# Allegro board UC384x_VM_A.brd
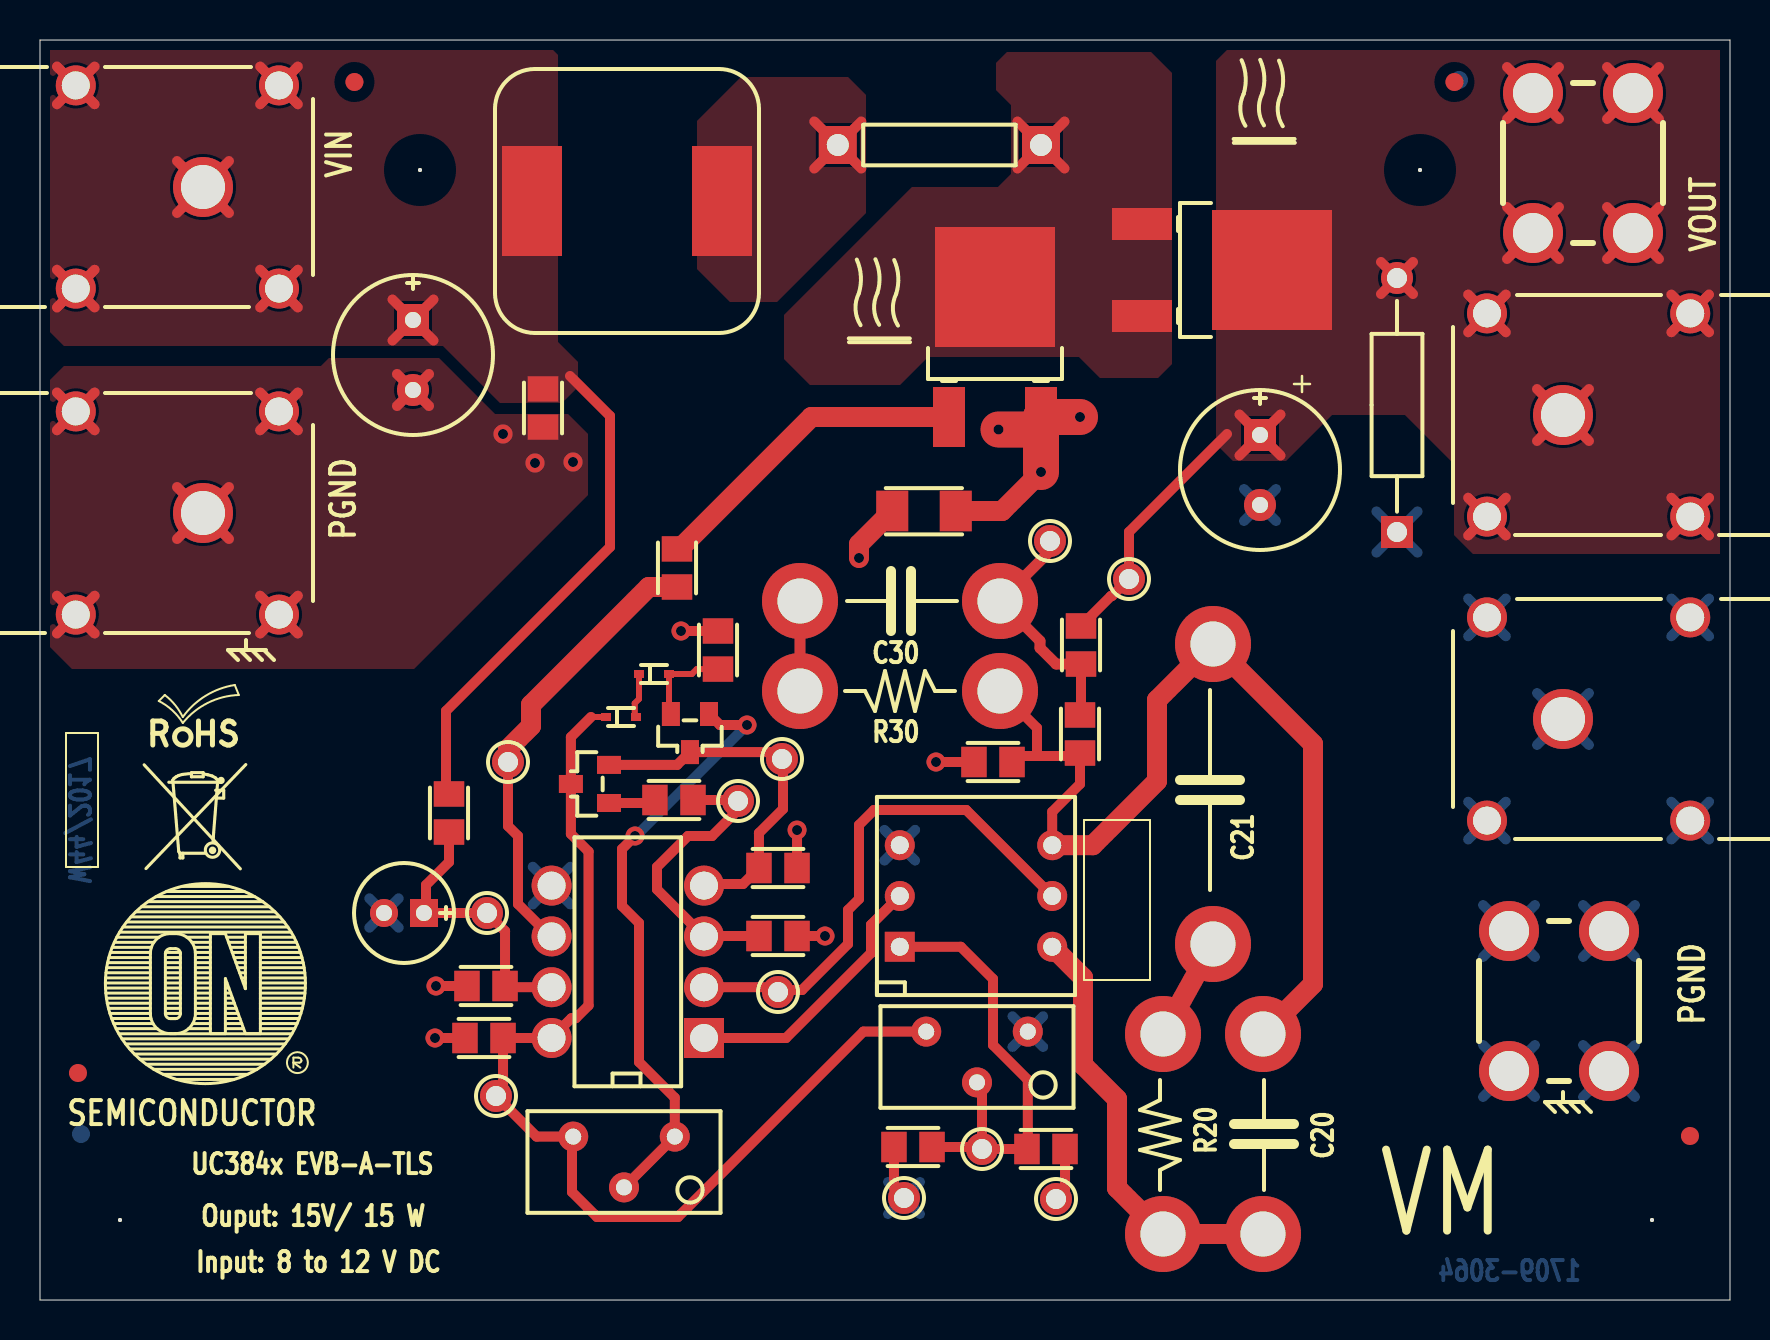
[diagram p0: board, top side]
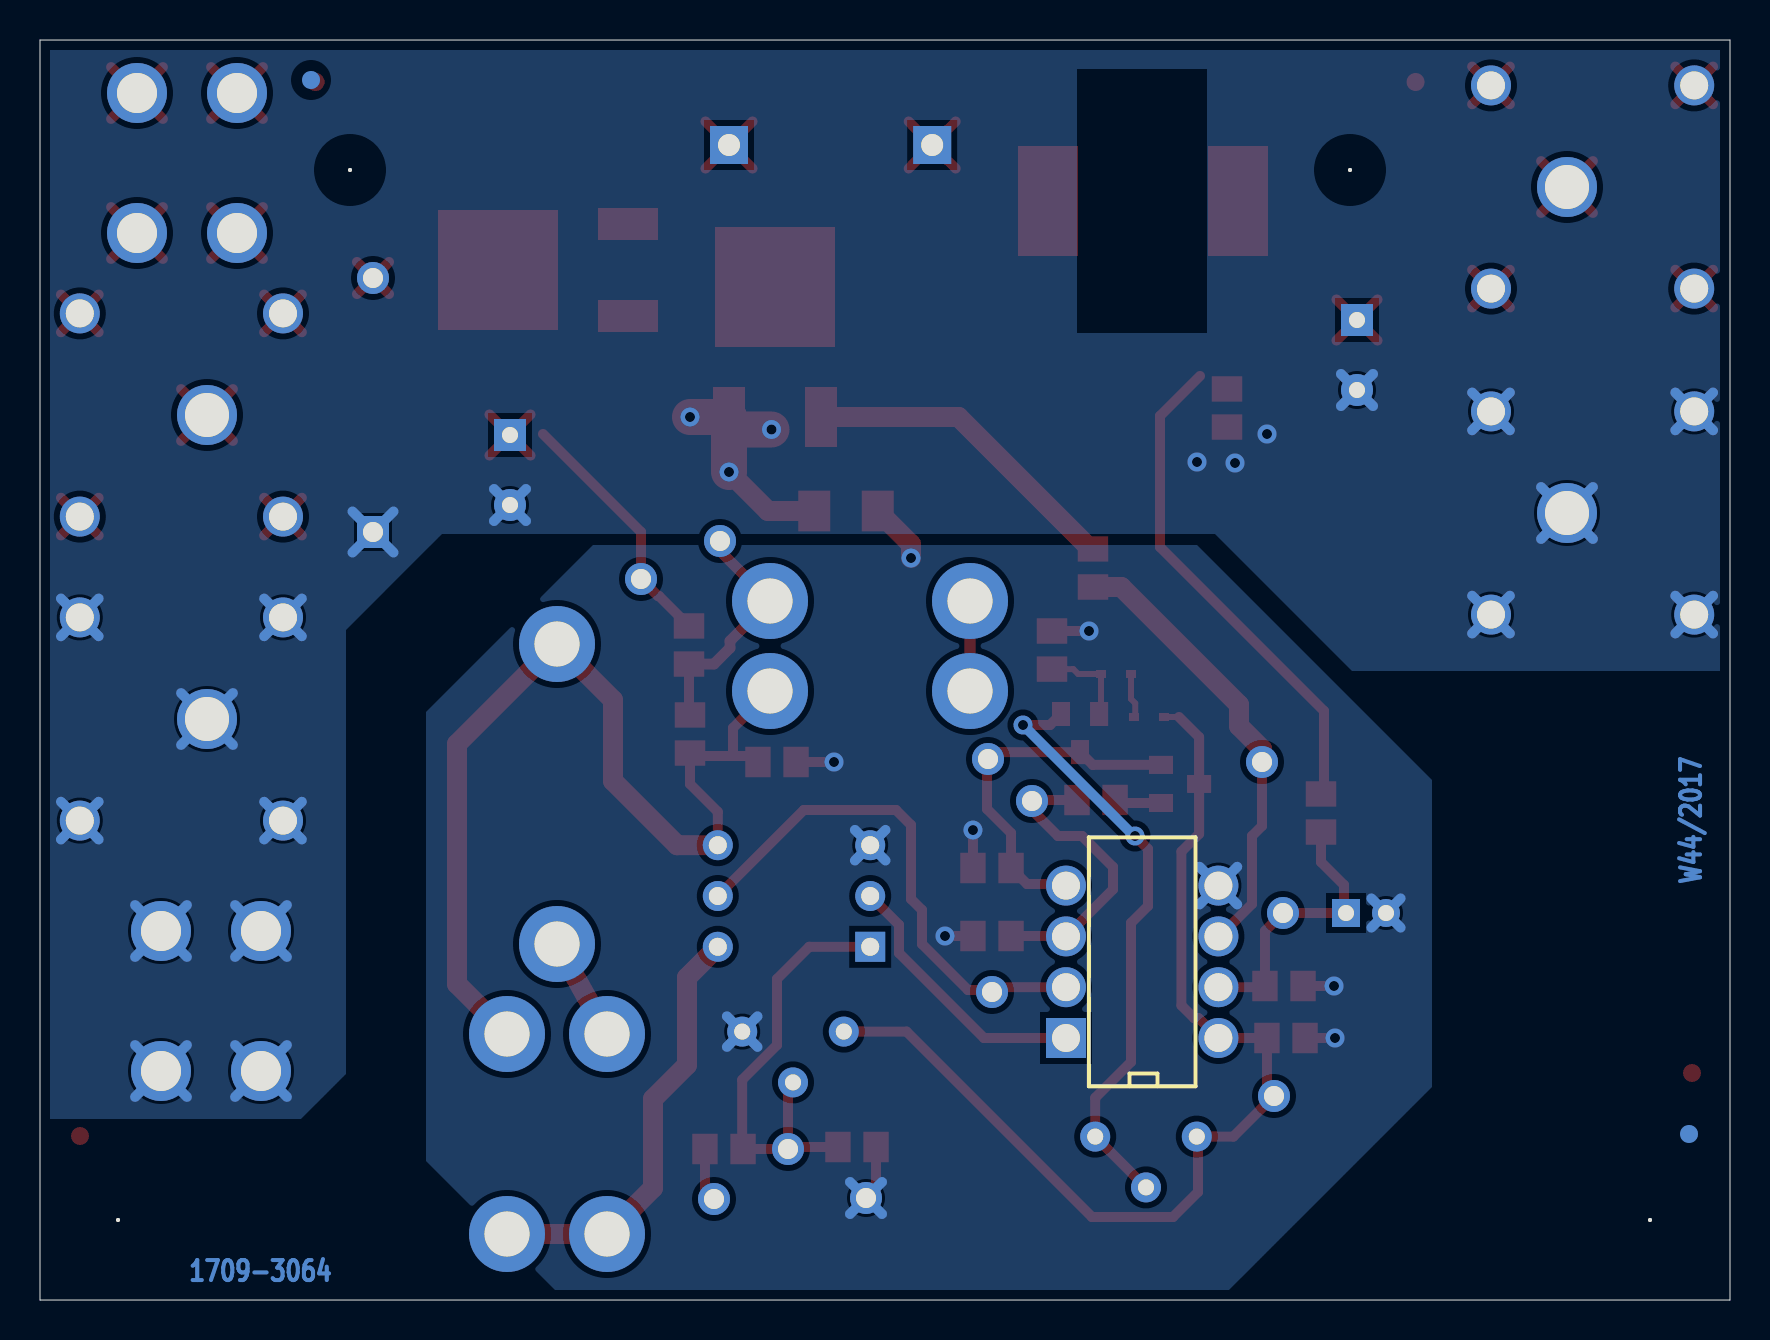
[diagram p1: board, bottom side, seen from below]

Outline 84.5 x 63 mm; copper layers: TOP, IN1, IN2, BOTTOM. Coordinates in mm from the lower left corner of the outline.
Outline path: 0,63 0,0 84.5,0 84.5,63 0,63

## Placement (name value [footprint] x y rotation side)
ACM_H  TEST POINT  [TP]  50.8 5.05 180 top
ACM_L  TEST POINT  [TP]  43.2 5.1 180 top
C1  100nF  [0805]  22.2 13.1 180 top
C1A  D  [PLOT_5380598-2]  58.65 32.8 270 top
C1B  D  [PLOT_5380598-2]  58.65 17.8 270 top
C2A  D  [PLOT_5380598-2]  61.15 13.3 270 top
C2B  D  [PLOT_5380598-2]  61.15 3.3 270 top
C3  2.2uF  [CAPA_CH_D5_H11_P2]  18.2 19.35 180 top
C3A  D  [PLOT_5380598-2]  38 34.95 0 top
C3B  D  [PLOT_5380598-2]  48 34.95 0 top
C4  220uF  [CAPA_CH_D8_H12_P3V5]  61 41.5 270 top
C5  220uF  [CAPA_CH_D8_H12_P3V5]  18.65 47.25 270 top
C6  1uF  [0805]  25.15 44.6 270 top
C7  100nF  [0805]  22.3 15.7 180 top
C8  100nF  [0805]  43.65 7.65 180 top
C9  2.2uF  [0805]  50.3 7.55 180 top
CB1  target_cms  [MIRE_LOW]  2.05 8.3 180 bottom
CB2  target_cms  [MIRE_LOW]  70.95 61 180 bottom
CB3  target_cms  [MIRE_LOW]  1.9 11.35 0 top
CB4  target_cms  [MIRE_LOW]  70.72 60.9 0 top
CB5  target_cms  [MIRE_LOW]  82.5 8.2 0 top
CB6  target_cms  [MIRE_LOW]  15.72 60.9 0 top
CMP  TEST POINT  [TP]  36.9 15.4 0 top
CT  1nF  [0805]  36.9 21.6 0 top
D1  1N4148  [SOD523]  29.05 29.15 0 top
D2  1N4148  [SOD523]  30.7 31.3 0 top
D3  MBRD1045T4G  [DPAK_TO252]  60 51.5 270 top
DRV  TEST POINT  [TP]  23.4 26.9 180 top
J1A  SLB4-I/90_R  [BANANE_4MM_SLB4]  8.15 55.65 180 top
J1B  SLB4-I/90_B  [BANANE_4MM_SLB4]  8.15 39.35 180 top
J1C  SLB4-I/90_R  [BANANE_4MM_SLB4]  76.15 44.25 0 top
J1D  SLB4-I/90_B  [BANANE_4MM_SLB4]  76.15 29.05 0 top
J2A  Screw_terminal  [PC_7701]  77.15 56.85 0 top
J2B  Screw_terminal  [PC_7701]  75.95 14.95 0 top
L1  180uH  [SELF_MSS1210]  29.35 54.95 90 top
NOREF  -  []  -114.15 -47.45 0 top
NOREF#2  -  []  84.5 0 90 top
NOREF#3  -  [unnamed#2]  19 56.5 0 top
NOREF#4  -  []  0 63 0 top
NOREF#5  -  [unnamed#2]  69 56.5 0 top
NOREF#6  -  [unnamed#2]  80.6 4 0 top
NOREF#7  -  []  80.6 4 0 top
NOREF#8  -  [unnamed#2]  4 4 0 top
NOREF#9  -  []  -181.6 -74.35 0 top
NOREF#10  -  []  84.5 0 90 top
NOREF#11  -  []  283.55 -63.75 180 bottom
OSC  TEST POINT  [TP]  37.1 27.05 0 top
P1  10K  [POTAR_12T_3266W]  46.85 12.15 180 top
P2  10K  [POTAR_12T_3266W]  29.2 6.9 180 top
Q1  NTD5865NLT4G  [DPAK_TO252]  47.75 49.05 0 top
Q2  2N2907A  [SOT23]  32.5 28.35 0 top
Q3  2N2222A  [SOT23]  27.5 25.8 270 top
R1  11K  [0805]  52 28.3 90 top
R2  10K  [0805]  33.9 32.5 270 top
R2A  D  [PLOT_5380598-2]  56.15 13.3 270 top
R2B  D  [PLOT_5380598-2]  56.15 3.3 270 top
R3  2.2K  [0805]  36.9 18.2 180 top
R3A  D  [PLOT_5380598-2]  48 30.45 0 top
R3B  D  [PLOT_5380598-2]  38 30.45 0 top
R4  2.7K  [0805]  31.7 25 180 top
R5  10R  [0805]  20.45 24.35 90 top
R7  2.2K  [0805]  47.65 26.9 0 top
R8  10R  [0805]  52.05 32.75 90 top
R9  10R  [0805]  31.85 36.6 90 top
R10  0R  [1206]  44.2 39.45 0 top
R11  1K / 0.5W  [RC21U]  67.85 44.75 90 top
S1  Strap  [JUMPER400H]  50.05 57.75 180 top
SAW  TEST POINT  [TP]  34.9 24.95 0 top
SW1  DPDT  [SW_76SD01ST]  46.8 20.2 0 top
U1  UC3845B  [DIP8_SUP]  33.2 13.1 180 top
VA  TEST POINT  [TP]  54.45 36.05 0 top
VB  TEST POINT  [TP]  50.5 37.95 0 top
VCC  TEST POINT  [TP]  22.35 19.35 180 top
VREF  TEST POINT  [TP]  22.8 10.2 0 top
VSET  TEST POINT  [TP]  47.1 7.55 180 top

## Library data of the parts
ACM_H ACM_L CMP DRV OSC S1 SAW VA VB VCC VREF VSET = TEST POINT_0
C1 C3 C6-C9 CT = C
C1A C1B C2A C2B C3A C3B R2A R2B R3A R3B = T POINT R_0
C4 C5 = C_elect_0
CB1-CB6 = target_cms
D1 D2 = D1N4148
D3 = dual_diodeAAK
J1A J1B J1C J1D = HEADER 1_0
J2A J2B = 4 HEADER_0
L1 = L
P1 P2 = RESISTOR VAR
Q1 = NMOS_3
Q2 = 2N2907A
Q3 = 2N2222A
R1-R5 R7-R9 R11 = R
R10 = R: alternate symbols: (RES_1W_D5XL12_jp)
SW1 = SW DPDT/SM_0
U1 = UC3845B

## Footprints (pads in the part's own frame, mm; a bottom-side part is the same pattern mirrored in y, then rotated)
0805
  rect 1.27x1.524 smd: 1(-0.953,0) 2(0.953,0)
1206
  rect 1.6x2.03 smd: 1(-1.587,0) 2(1.587,0)
BANANE_4MM_SLB4
  round 3 hole 2.2: 1(0,0)
  round 2 hole 1.4: 2(-3.8,5.08) 3(-3.8,-5.08) 4(6.36,5.08) 5(6.36,-5.08)
CAPA_CH_D5_H11_P2
  rect 1.4x1.4 hole 0.8: 1(-1,0)
  round 1.4 hole 0.8: 2(1,0)
CAPA_CH_D8_H12_P3V5
  rect 1.6x1.6 hole 0.8: 1(-1.75,0)
  round 1.6 hole 0.8: 2(1.75,0)
DIP8_SUP
  rect 2x2 hole 1.4: 1(0,0)
  round 2 hole 1.4: 2(0,-2.54) 3(0,-5.08) 4(0,-7.62) 5(7.62,-7.62) 6(7.62,-5.08) 7(7.62,-2.54) 8(7.62,0)
DPAK_TO252
  rect 1.6x3 smd: 1(-2.3,-4.9) 3(2.3,-4.9)
  rect 6x6 smd: 2(0,1.6)
JUMPER400H
  rect 1.9x1.9 hole 1.1: 1(0,0) 2(10.16,0)
MIRE_LOW
  round 0.9 smd: 1(0,0)
PC_7701
  round 3 hole 2: 1(-2.5,-3.5) 2(2.5,-3.5) 3(2.5,3.5) 4(-2.5,3.5)
PLOT_5380598-2
  round 3.8 hole 2.25: 1(0,0)
POTAR_12T_3266W
  round 1.5 hole 0.8: 1(-2.54,-1.27) 2(0,1.27) 3(2.54,-1.27)
RC21U
  rect 1.6x1.6 hole 1: 1(-6.35,0)
  round 1.6 hole 1: 2(6.35,0)
SELF_MSS1210
  rect 5.5x3 smd: 1(0,4.75) 2(0,-4.75)
SOD523
  rect 0.5x0.4 smd: 1(-0.75,0) 2(0.75,0)
SOT23
  rect 0.9x1.2 smd: 1(0.953,0.953) 2(-0.953,0.953) 3(0,-0.953)
SW_76SD01ST
  rect 1.5x1.5 hole 0.9: 1(-3.81,-2.54)
  round 1.5 hole 0.9: 2(-3.81,2.54) 11(3.81,-2.54) 22(3.81,2.54) C1(-3.81,0) C2(3.81,0)
TP
  round 1.6 hole 1: 1(0,0)
unnamed#2
  round 0.2 hole 3 unplated: (0,0)

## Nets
GND_EARTH: ACM_L.1 C1.2 C3.2 C7.2 C8.2 CT.2 P1.1(A) R2.1 R3.1 R7.1 R10.1 SW1.2(NO2) U1.5(GND)
GND_SIGNAL: C4.2(-) C5.2(-) C6.2 J1B.1 J1B.2 J1B.3 J1B.4 J1B.5 J1D.1 J1D.2 J1D.3 J1D.4 J1D.5 J2B.1 J2B.2 J2B.3 J2B.4 Q1.3(S) R10.2 R11.1
VCC: C3.1 C7.1 R5.1 U1.7(VCC) VCC.1
VIN: C5.1(+) C6.1 J1A.1 J1A.2 J1A.3 J1A.4 J1A.5 L1.1 R5.2
DRV: DRV.1 R9.1 U1.6(DRV)
REF: C1.1 D1.1 P1.3(B) P2.3(B) Q3.3(COLLECTOR) U1.8(REF) VREF.1
VOUT: C4.1(+) D3.2(C) J1C.1 J1C.2 J1C.3 J1C.4 J1C.5 J2A.1 J2A.2 J2A.3 J2A.4 R8.2 R11.2 VA.1
N12290274: L1.2 S1.2
N12290314: D3.1(A1) D3.3(A2) Q1.2(D) S1.1
N12292005: Q1.1(G) R9.2
N12295469: CT.1 OSC.1 Q2.3(COLLECTOR) Q3.2(BASE) U1.4(RT/CT)
N12295845: R3.2 R4.1 SAW.1 U1.3(IS)
N12296104: CMP.1 SW1.C2(COMMON2) U1.2(FB)
N12296108: SW1.C1(COMMON1) U1.1(EA)
N12297349: C3B.1(TP) R1.2 R8.1 VB.1
N12298127: C1A.1(TP) C2A.1(TP) R1.1 R3A.1(TP) R7.2 SW1.22(NC2)
N12298463: C8.1 C9.2 P1.2(WIPER) SW1.1(NO1) VSET.1
N12299817: C1B.1(TP) R2A.1(TP)
N12299821: C2B.1(TP) R2B.1(TP) SW1.11(NC1)
N12301916: ACM_H.1 C9.1
N12308692: P2.1(A) P2.2(WIPER) Q2.1(EMITTER)
N12308941: D2.2 Q2.2(BASE) R2.2
N12308973: D1.2 D2.1
N12309768: C3A.1(TP) R3B.1(TP)
N122961380: Q3.1(EMITTER) R4.2

Pads without a net: CB1 1; CB2 1; CB3 1; CB4 1; CB5 1; CB6 1

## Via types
v1: diameter 0.95, hole 0.5, TOP to BOTTOM, 15 vias

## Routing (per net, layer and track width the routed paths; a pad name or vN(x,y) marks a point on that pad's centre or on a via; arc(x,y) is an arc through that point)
GND_EARTH: length 38.5
  TOP w0.5: CT.2 v1(37.85,23.5) ; R3.1 v1(39.25,18.2) ; C8.2 42.7,5.6 ACM_L.1 ; R2.1 v1(32.05,33.45) ; C1.2 v1(19.75,13.1) ; C7.2 v1(19.8,15.7) ; R7.1 v1(44.8,26.9)
  TOP w1: R10.1 40.95,37.79 v1(40.95,37.1)
  BOTTOM w0.5: P1.1 50.15,14.18 ; P1.1 50.15,12.66 ; P1.1 48.63,14.18 ; P1.1 48.63,12.66 ; 42.23,23.5 SW1.2 ; SW1.2 43.75,21.98 ; SW1.2 43.75,23.5 ; SW1.2 42.23,21.98 ; 16.47,20.08 C3.2 ; C3.2 17.93,20.08 ; C3.2 17.93,18.62 ; C3.2 16.47,18.62 ; 24.64,19.78 U1.5 ; U1.5 26.52,21.66 ; U1.5 26.52,19.78 ; U1.5 24.64,21.66 ; 42.4,4.3 ACM_L.1 ; ACM_L.1 42.4,5.9 ; ACM_L.1 44,4.3 ; ACM_L.1 44,5.9
GND_SIGNAL: length 146.6
  TOP w0.5: J1B.4 2.73,33.33 ; J1B.4 2.73,35.21 ; J1B.4 0.85,35.21 ; J1B.4 0.85,33.33 ; 6.86,40.64 J1B.1 ; J1B.1 9.44,38.06 ; J1B.1 6.86,38.06 ; J1B.1 9.44,40.64 ; J1B.2 12.89,35.21 ; J1B.2 11.01,33.33 ; J1B.2 11.01,35.21 ; J1B.2 12.89,33.33 ; 0.85,43.49 J1B.5 ; J1B.5 2.73,43.49 ; J1B.5 2.73,45.37 ; J1B.5 0.85,45.37 ; C5.2 19.45,46.3 ; C5.2 19.45,44.7 ; C5.2 17.85,46.3 ; C5.2 17.85,44.7 ; 11.01,45.37 J1B.3 ; J1B.3 12.89,45.37 ; J1B.3 11.01,43.49 ; J1B.3 12.89,43.49
  TOP w1: R10.2 48.1,39.45 v1(50.05,41.4)
  TOP w1.8: v1(47.92,43.52) 49.77,43.52 50.05,43.24 ; v1(52,44.15) Q1.3 50.05,43.24 ; 50.05,43.24 v1(50.05,41.4)
  BOTTOM w0.5: 81.57,35.07 J1D.4 ; J1D.4 81.57,33.19 ; J1D.4 83.45,35.07 ; J1D.4 83.45,33.19 ; C4.2 61.8,38.95 ; C4.2 60.2,40.55 ; C4.2 61.8,40.55 ; C4.2 60.2,38.95 ; J2B.2 79.74,10.16 ; J2B.2 77.16,12.74 ; J2B.2 77.16,10.16 ; J2B.2 79.74,12.74 ; J1D.3 73.29,24.91 ; J1D.3 71.41,23.03 ; J1D.3 73.29,23.03 ; J1D.3 71.41,24.91 ; 66.82,37.37 R11.1 ; R11.1 66.82,39.43 ; R11.1 68.88,39.43 ; R11.1 68.88,37.37 ; 72.16,19.74 J2B.4 ; J2B.4 74.74,19.74 ; J2B.4 74.74,17.16 ; J2B.4 72.16,17.16 ; 77.16,17.16 J2B.3 ; J2B.3 79.74,17.16 ; J2B.3 77.16,19.74 ; J2B.3 79.74,19.74 ; C5.2 19.45,44.7 ; C5.2 19.45,46.3 ; C5.2 17.85,46.3 ; C5.2 17.85,44.7 ; J1D.2 73.29,35.07 ; J1D.2 73.29,33.19 ; J1D.2 71.41,33.19 ; J1D.2 71.41,35.07 ; 0.85,45.37 J1B.5 ; J1B.5 2.73,43.49 ; J1B.5 0.85,43.49 ; J1B.5 2.73,45.37 ; J1B.3 12.89,45.37 ; J1B.3 12.89,43.49 ; J1B.3 11.01,45.37 ; J1B.3 11.01,43.49 ; J1B.1 9.44,40.64 ; J1B.1 6.86,40.64 ; J1B.1 9.44,38.06 ; J1B.1 6.86,38.06 ; 81.57,23.03 J1D.5 ; J1D.5 83.45,24.91 ; J1D.5 83.45,23.03 ; J1D.5 81.57,24.91 ; 11.01,33.33 J1B.2 ; J1B.2 11.01,35.21 ; J1B.2 12.89,33.33 ; J1B.2 12.89,35.21 ; J1B.4 2.73,33.33 ; J1B.4 0.85,35.21 ; J1B.4 0.85,33.33 ; J1B.4 2.73,35.21 ; 72.16,10.16 J2B.1 ; J2B.1 74.74,10.16 ; J2B.1 74.74,12.74 ; J2B.1 72.16,12.74 ; J1D.1 77.44,27.76 ; J1D.1 74.86,30.34 ; J1D.1 77.44,30.34 ; J1D.1 74.86,27.76
  vias: v1(23.15,43.3) v1(24.75,41.85) v1(26.65,41.9)
VCC: length 14.1
  TOP w0.5: U1.7 23.31,15.64 C7.1 23.25,18.45 VCC.1 C3.1 19.3,19.45 19.3,20.75 20.45,21.9 R5.1
VIN: length 59.6
  TOP w0.5: 6.86,56.94 J1A.1 ; J1A.1 6.86,54.36 ; J1A.1 9.44,56.94 ; J1A.1 9.44,54.36 ; 0.85,49.63 J1A.4 ; J1A.4 2.73,49.63 ; J1A.4 2.73,51.51 ; J1A.4 0.85,51.51 ; J1A.3 12.89,61.67 ; J1A.3 11.01,59.79 ; J1A.3 11.01,61.67 ; J1A.3 12.89,59.79 ; 17.62,47.97 C5.1 ; C5.1 17.62,50.03 ; C5.1 19.68,47.97 ; C5.1 19.68,50.03 ; J1A.2 12.89,49.63 ; J1A.2 11.01,51.51 ; J1A.2 12.89,51.51 ; J1A.2 11.01,49.63 ; J1A.5 2.73,61.67 ; J1A.5 2.73,59.79 ; J1A.5 0.85,61.67 ; J1A.5 0.85,59.79 ; R5.2 20.3,25.45 20.3,29.45 28.5,37.65 28.5,44.2 26.5,46.2
DRV: length 22.7
  TOP w0.5: U1.6 25.52,18.18 23.9,19.8 23.9,23.2 23.4,23.7 DRV.1
  TOP w1: DRV.1 23.4,27.55 24.55,28.7 24.55,29.76 30.44,35.65 R9.1
REF: length 53.5
  TOP w0.3: D1.1 27.55,29.15
  TOP w0.5: P1.3 41.17,13.42 31.9,4.15 27.85,4.15 26.6,5.4 26.6,8.11 P2.3 24.83,8.17 VREF.1 23.15,10.55 C1.1 U1.8 26.57,14.09 26.79,14.09 27.43,14.73 27.43,22.42 26.55,23.3 Q3.3 26.55,28.14 27.55,29.15
VOUT: length 80.9
  TOP w0.5: 74.86,42.96 J1C.1 ; J1C.1 77.44,45.54 ; J1C.1 74.86,45.54 ; J1C.1 77.44,42.96 ; C4.1 62.03,44.28 ; C4.1 59.97,44.28 ; C4.1 62.03,42.22 ; C4.1 59.97,42.22 ; R11.2 68.65,51.9 ; R11.2 67.05,50.3 ; R11.2 67.05,51.9 ; R11.2 68.65,50.3 ; J1C.5 83.45,40.11 ; J1C.5 81.57,38.23 ; J1C.5 81.57,40.11 ; J1C.5 83.45,38.23 ; J1C.4 83.45,50.27 ; J1C.4 81.57,50.27 ; J1C.4 83.45,48.39 ; J1C.4 81.57,48.39 ; R8.2 53.55,35.2 53.6,35.2 VA.1 54.45,38.4 59.35,43.3 ; J1C.3 73.29,40.11 ; J1C.3 71.41,38.23 ; J1C.3 71.41,40.11 ; J1C.3 73.29,38.23 ; 73.36,52.06 J2A.1 ; J2A.1 75.94,54.64 ; J2A.1 73.36,54.64 ; J2A.1 75.94,52.06 ; J2A.4 75.94,61.64 ; J2A.4 73.36,59.06 ; J2A.4 73.36,61.64 ; J2A.4 75.94,59.06 ; J1C.2 73.29,50.27 ; J1C.2 71.41,48.39 ; J1C.2 73.29,48.39 ; J1C.2 71.41,50.27 ; J2A.3 80.94,61.64 ; J2A.3 80.94,59.06 ; J2A.3 78.36,59.06 ; J2A.3 78.36,61.64 ; J2A.2 80.94,52.06 ; J2A.2 78.36,52.06 ; J2A.2 78.36,54.64 ; J2A.2 80.94,54.64
N12290274: length 6.6
  TOP w0.5: 38.71,58.93 S1.2 ; S1.2 41.07,58.93 ; S1.2 38.71,56.57 ; S1.2 41.07,56.57
N12290314: length 6.6
  TOP w0.5: S1.1 51.23,56.57 ; S1.1 48.87,56.57 ; S1.1 48.87,58.93 ; S1.1 51.23,58.93
N12292005: length 16.3
  TOP w1: Q1.1 38.57,44.15 31.98,37.55 R9.2
N12295469: length 18.1
  TOP w0.5: U1.4 33.28,20.8 35.15,20.8 CT.1 35.95,23.35 37.15,24.55 37.15,27 OSC.1 36.76,27.39 Q2.3 31.86,26.75 Q3.2
N12295845: length 15.2
  TOP w0.5: R3.2 33.22,18.2 U1.3 30.85,20.53 30.85,21.65 32.4,23.2 33.6,23.2 34.9,24.5 SAW.1 34.85,25 R4.1
N12296104: length 26.5
  TOP w0.5: 36.66,15.64 CMP.1 ; 36.66,15.64 U1.2 ; 36.66,15.64 36.76,15.64 36.9,15.5 38.1,15.5 40.4,17.8 40.4,19.5 40.95,20.05 40.95,23.75 41.7,24.5 46.31,24.5 SW1.C2
N12296108: length 13.6
  TOP w0.5: SW1.C1 41.55,18.76 41.55,17.35 37.3,13.1 U1.1
N12297349: length 12.2
  TOP w0.5: R1.2 52.05,29.3 R8.1
  TOP w0.54: VB.1 50.5,37.45 C3B.1 50,32.95 50,32.6 50.8,31.8 R8.1
N12298127: length 50
  TOP w0.5: R7.2 48.9,27.2 49.85,27.2 ; SW1.22 50.61,24.41 52,25.8 R1.1 51.85,27.2 49.85,27.2 ; 49.85,27.2 49.85,28.6 R3A.1
  TOP w1: SW1.22 52.64,22.74 55.85,25.95 55.85,30 C1A.1 63.65,27.8 63.65,15.8 C2A.1
N12298463: length 22.8
  TOP w0.5: SW1.1 46.04,17.66 47.65,16.05 47.65,12.75 49.39,11.01 49.39,7.59 C9.2 VSET.1 ; VSET.1 47.1,10.63 P1.2 ; VSET.1 47,7.65 C8.1
N12299817: length 5.1
  TOP w1: C1B.1 R2A.1
N12299821: length 21.7
  TOP w1: C2B.1 R2B.1 53.85,5.6 53.85,10.05 52.15,11.75 52.15,16.12 SW1.11
N12301916: length 2.7
  TOP w0.5: C9.1 51.25,5.5 ACM_H.1
N12308692: length 30
  TOP w0.5: Q2.1 34,28.75 v1(35.35,28.75) ; P2.2 P2.1 31.74,10.11 29.95,11.9 29.95,18.85 29.1,19.7 29.1,22.55 v1(29.75,23.2)
  BOTTOM w0.5: v1(35.35,28.75) 29.8,23.2 v1(29.75,23.2)
N12308941: length 4.6
  TOP w0.3: R2.2 32.84,31.55 32.59,31.3 D2.2 31.45,29.39 Q2.2
N12308973: length 2.3
  TOP w0.3: D1.2 29.74,29.21 29.74,29.84 29.95,30.05 D2.1
N12309768: length 4.5
  TOP w0.54: R3B.1 C3A.1
N122961380: length 2.4
  TOP w0.5: R4.2 30.59,24.85 Q3.1

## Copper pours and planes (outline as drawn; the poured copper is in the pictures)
GND_EARTH on BOTTOM: 25.05,0.5 14.9,10.65 14.9,26 26.65,37.75 56.85,37.75 65.2,29.4 65.2,6.95 58.75,0.5
GND_SIGNAL on TOP: 1.6,31.55 0.5,32.65 0.5,46 1.2,46.7 14.05,46.7 14.45,47.1 19.95,47.1 22.75,44.3 26.4,44.3 27.4,43.3 27.4,40.25 18.7,31.55
GND_SIGNAL on BOTTOM: 71.45,9.05 69.2,11.3 69.2,33.5 64.4,38.3 25.75,38.3 18.9,31.45 0.5,31.45 0.5,62.5 84,62.5 84,9.05
VIN on TOP: 23,44.85 20.15,47.7 1.2,47.7 0.5,48.4 0.5,62.5 25.65,62.5 25.9,62.25 25.9,47.9 26.9,46.9 26.9,45.65 26.1,44.85
Net_29 on IN2: 0,0 0,53 83.5,53 83.5,0
VOUT on TOP: 71.65,37.3 70.7,38.25 70.7,41.8 68.25,44.25 64.6,44.25 62.3,41.95 59.65,41.95 58.8,42.8 58.8,61.95 59.35,62.5 84,62.5 84,37.3
N12290274 on TOP: 41.3,54.35 41.3,60.25 40.4,61.15 35.05,61.15 32.85,58.95 32.85,51.55 34.5,49.9 36.85,49.9
N12290314 on TOP: 48.55,59.75 48.55,56.3 47.9,55.65 43.6,55.65 37.2,49.25 37.2,47.05 38.5,45.75 43,45.75 44.4,47.15 51.95,47.15 53,46.1 55.9,46.1 56.6,46.8 56.6,61.35 55.55,62.4 48.35,62.4 47.8,61.85 47.8,60.5

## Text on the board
BOTTOM: BOT 1/1 | 1709-3064 | W44/2017
Ref Des/Silkscreen Bottom: SILK_BOT
User.Comments: VE_BOT | VE_TOP
TOP: TOP 2/2
Ref Des/Silkscreen Top: UC384x EVB-A-TLS | Input: 8 to 12 V DC | Ouput: 15V/ 15 W | C30 | R30 | R20 | C21 | C20 | SEMICONDUCTOR | SILK_TOP | VIN | PGND | VOUT | VM
IN1: IN1 3/4
IN2: IN2 2/4
DIMENSION: 1.0 | VM
BODY_CENTER: 1.0
User.5: CHEMICAL NiAu | 35um(1oz)at START | THICKNESS | MATERIAL | STACKUP | FINISH | SILKSCREEN | MINIMAL GAP | MINIMAL SLIVER | BOARD THICKNESS | SOLDER MASK | COPPER THICKNESS | MARKED ON BOTTOM SOLDERMASK | ALL BOARD ELECTRICALLY TESTED | MANUFACTURE 'S LOGO & DATECODE | COMPLIANT RoHS DIRECTIVE 2011/65/UE | DF /2LAYERS | WHITE TOP | FR4 IMPROVED (low CTE) | 210um /8.0mils | GREEN TOP & BOT | 1.6mm /63mils | 1.0 | VM | SPEC:
User.6: DEMO UC384x 1709-3064   W44/2017
User.7: FIGURE | SIZE | 0.5 | 0.8 | 0.9 | 1.0 | 1.1 | 1.4 | 2.0 | 2.2 | 2.25 | 3.0 | DRILL CHART: TOP to BOTTOM | ALL UNITS ARE IN MILLIMETERS | TOLERANCE | +0.0/-0.0 | +0.05/-0.05 | PLATED | NON-PLATED | QTY | 15 | 2 | 6 | 4 | 13 | 8 | 16 | 10
